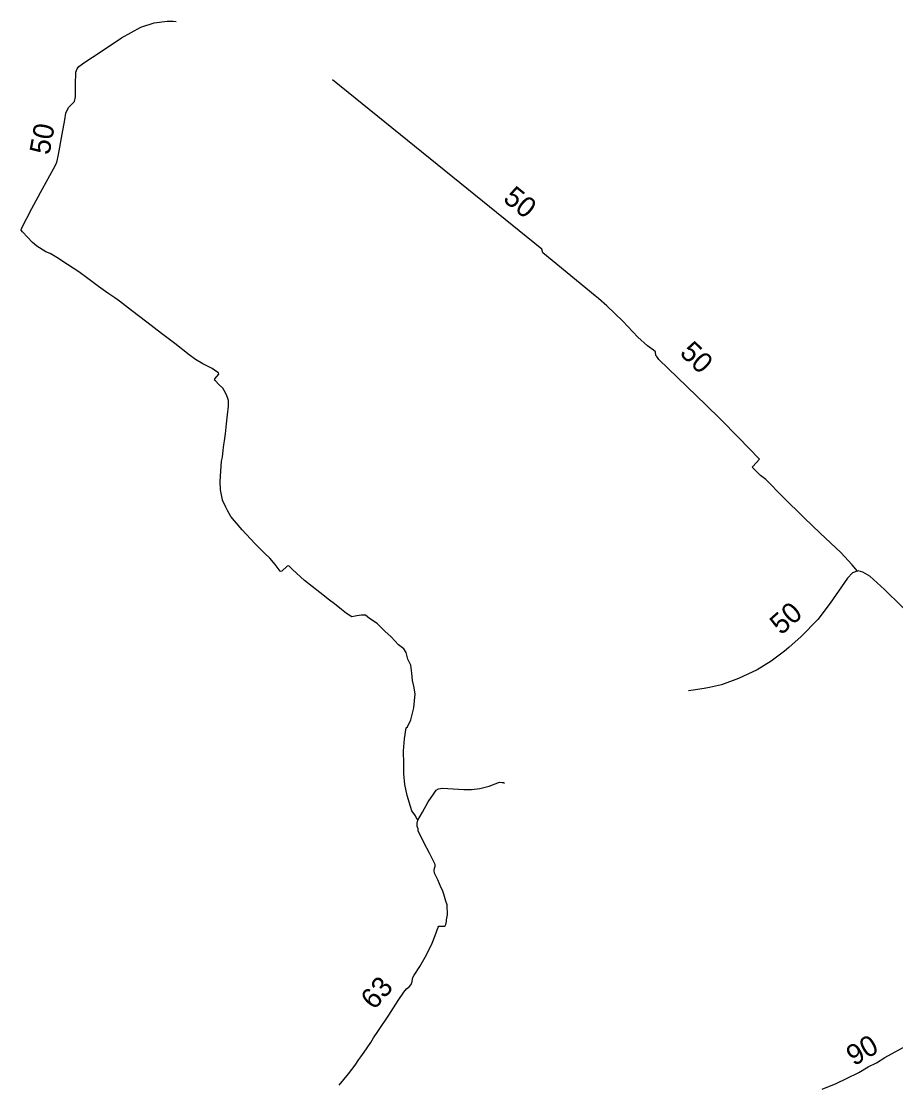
# Model space of a CAD drawing. Extents: x -444841 to -429545, y -1135312 to -1129851.
# Drawn here: x -442958 to -442616.2, y -1130962.1 to -1130546.7 of the extents above; entities that cross this region are included whole.
import ezdxf

# ---------------------------------------------------------------- set-up
doc = ezdxf.new("R2010")
doc.units = 0
for name, color, linetype in [('Vrstva 27', 7, 'Continuous'), ('Vrstva 30', 7, 'Continuous'), ('Vrstva 35', 7, 'Continuous'), ('Vrstva 38', 7, 'Continuous')]:
    doc.layers.add(name, color=color, linetype=linetype)

msp = doc.modelspace()

# ---------------------------------------------------------------- linework, layer by layer
at = {"layer": 'Vrstva 27'}
for points in [[(-442948.46, -1130636.83), (-442951.87, -1130634.68), (-442953.67, -1130633.16), (-442957.48, -1130629.04), (-442958.02, -1130628.37), (-442957.91, -1130627.65), (-442953.91, -1130619.91), (-442949.7, -1130612.21), (-442945.35, -1130604.37), (-442944.09, -1130601.96), (-442943.43, -1130598.8), (-442941.97, -1130590.85), (-442940.93, -1130585.18), (-442940.54, -1130582.6), (-442939.6, -1130580.36), (-442937.16, -1130578.11), (-442936.75, -1130576.27), (-442936.83, -1130571.51), (-442936.69, -1130566.66), (-442936.2, -1130565.3), (-442935.54, -1130564.39), (-442933.22, -1130562.69), (-442927.13, -1130558.77), (-442918.83, -1130553.17), (-442911.3, -1130548.95), (-442906.12, -1130547.37), (-442900.95, -1130546.69), (-442898.69, -1130546.72), (-442897.52, -1130546.8)], [(-442832.8, -1130776.69), (-442835.56, -1130774.5), (-442837.51, -1130772.98), (-442841.34, -1130769.98), (-442847.34, -1130765.3), (-442852.04, -1130761.08), (-442853.33, -1130759.71), (-442853.74, -1130759.58), (-442854.05, -1130759.7), (-442856.16, -1130761.61), (-442856.43, -1130761.77), (-442856.8, -1130761.66), (-442857.2, -1130761.13), (-442858.77, -1130759.04), (-442860.9, -1130756.63), (-442862.96, -1130754.69), (-442866.77, -1130750.91), (-442871.63, -1130745.45), (-442874.71, -1130741.99), (-442876.12, -1130740.32), (-442877.41, -1130738.02), (-442878.05, -1130736.62), (-442879.31, -1130733.89), (-442879.34, -1130733.82), (-442880.12, -1130729.93), (-442880.24, -1130726.64), (-442879.98, -1130722.59), (-442879.93, -1130720.68), (-442879.75, -1130718.71), (-442879.38, -1130717.07), (-442879.03, -1130714.37), (-442878.79, -1130712.29), (-442878.53, -1130710.66), (-442878.17, -1130707.99), (-442877.73, -1130704.1), (-442877.36, -1130700.56), (-442877.06, -1130697.13), (-442876.96, -1130694.99), (-442877.43, -1130693.8), (-442877.65, -1130693.09), (-442878.16, -1130691.99), (-442879.28, -1130690.17), (-442880.76, -1130688.64), (-442882.14, -1130687.3), (-442882.47, -1130686.97), (-442882.39, -1130686.52), (-442880.78, -1130684.71), (-442880.73, -1130684.65), (-442880.87, -1130684.18), (-442881.51, -1130683.78), (-442883.42, -1130682.5), (-442887.04, -1130680.61), (-442889.84, -1130678.89), (-442892.38, -1130677.09), (-442897.92, -1130672.65), (-442903.24, -1130668.76), (-442908.93, -1130664.36), (-442914.87, -1130659.82), (-442919.66, -1130656.15), (-442921.43, -1130654.84), (-442924.16, -1130653.04), (-442927.86, -1130650.36), (-442931.98, -1130647.32), (-442935.48, -1130644.67), (-442939.94, -1130641.73), (-442944.13, -1130639.08), (-442946.77, -1130637.43), (-442948.46, -1130636.83)], [(-442631.13, -1130761.67), (-442633.22, -1130759.18), (-442637.66, -1130754.31), (-442645.64, -1130746.8), (-442652, -1130740.82), (-442660.31, -1130732.56), (-442666.92, -1130725.88), (-442669.04, -1130724.31), (-442672.06, -1130721.31), (-442672.23, -1130721.05), (-442672.06, -1130720.75), (-442669.36, -1130717.93), (-442677.57, -1130709.44), (-442684.69, -1130702.29), (-442690.38, -1130696.7), (-442694.05, -1130693.1), (-442701.54, -1130685.97), (-442708.79, -1130678.92), (-442709.62, -1130677.75), (-442709.92, -1130677.36), (-442710.08, -1130675.98), (-442710.88, -1130675.26), (-442713.18, -1130673.54), (-442717, -1130670.16), (-442722.91, -1130663.98), (-442729.07, -1130658), (-442732.37, -1130655.02), (-442733.63, -1130654.08), (-442734.2, -1130653.65)], [(-442631.13, -1130761.67), (-442631.29, -1130761.72), (-442633.01, -1130762.3), (-442634.97, -1130764.35), (-442641.8, -1130774.19), (-442646.64, -1130780.62), (-442653.07, -1130787.17), (-442657.97, -1130791.51), (-442659.65, -1130793), (-442664.92, -1130796.9), (-442670.3, -1130800.21), (-442677.67, -1130803.68), (-442684.33, -1130806.12), (-442688.95, -1130807.11), (-442691.11, -1130807.51), (-442695.3, -1130808.24), (-442697.13, -1130808.46)], [(-442602.71, -1130779.69), (-442603.48, -1130779.37), (-442604.45, -1130779.32), (-442606.52, -1130781.39), (-442606.86, -1130781.47), (-442607.46, -1130781.28), (-442613.91, -1130775.41), (-442620.53, -1130768.88), (-442626.35, -1130763.61), (-442629.05, -1130762.08), (-442630.9, -1130761.59), (-442631.13, -1130761.67)], [(-442833.76, -1130962.64), (-442830.14, -1130958.16), (-442827.51, -1130954.79), (-442826, -1130952.6), (-442825.27, -1130951.56), (-442823.96, -1130949.76), (-442821.41, -1130945.88), (-442820.26, -1130944.13), (-442818.61, -1130941.62), (-442818.36, -1130941.23), (-442814.37, -1130935.29), (-442810.63, -1130929.55), (-442808.52, -1130926.29), (-442807.39, -1130925.01), (-442806.35, -1130924.23), (-442805.65, -1130923.28), (-442805.17, -1130922.08), (-442805.03, -1130921.18), (-442804.98, -1130920.58), (-442804.44, -1130919.67), (-442802.26, -1130916.22), (-442799.64, -1130911.63), (-442797.43, -1130907.11), (-442796.22, -1130904.05), (-442795.03, -1130900.85), (-442794.77, -1130900.47), (-442794.4, -1130900.43), (-442793.6, -1130900.42), (-442793.13, -1130900.43), (-442792.49, -1130900.44), (-442792.31, -1130900.36), (-442792.04, -1130899.8), (-442791.84, -1130898.69), (-442791.73, -1130897.99), (-442791.44, -1130896.02), (-442791.5, -1130892.12), (-442791.98, -1130890.66), (-442792.78, -1130887.95), (-442793.33, -1130886.43), (-442793.81, -1130885.44), (-442795.16, -1130882.39), (-442796.46, -1130879.79), (-442796.56, -1130878.68), (-442796.52, -1130877.84), (-442796.22, -1130877.14), (-442796.24, -1130876.36), (-442796.7, -1130875.34), (-442798.48, -1130871.95), (-442800.6, -1130867.78), (-442802.82, -1130863.18), (-442802.88, -1130862.46), (-442803.26, -1130861.45), (-442803.2, -1130860.18), (-442803.04, -1130858.98), (-442803.2, -1130858.69), (-442803.85, -1130857.32), (-442805.35, -1130855.35), (-442805.9, -1130853.69), (-442807.15, -1130849.37), (-442808.06, -1130845.03), (-442808.48, -1130840.85), (-442808.44, -1130837.12), (-442808.65, -1130831.96), (-442808.19, -1130827.16), (-442807.51, -1130822.86), (-442807.06, -1130822.47), (-442805.77, -1130819.78), (-442804.56, -1130815.08), (-442804.01, -1130809.6), (-442804.58, -1130806.68), (-442805.05, -1130804.47), (-442805.29, -1130801.49), (-442805.78, -1130798.43), (-442806.84, -1130796.11), (-442807.58, -1130793.48), (-442808.51, -1130792.09), (-442810.59, -1130790.46), (-442813.35, -1130787.28), (-442815.89, -1130785.07), (-442818.93, -1130782.19), (-442821.92, -1130780.16), (-442823.4, -1130778.91), (-442825, -1130778.91), (-442826.86, -1130779.16), (-442828.73, -1130779.47), (-442830.85, -1130778.23), (-442832.8, -1130776.69)], [(-442803.04, -1130858.98), (-442801.14, -1130855.89), (-442798.98, -1130851.88), (-442796.91, -1130848.81), (-442795.82, -1130847.35), (-442794.93, -1130846.77), (-442793.32, -1130846.5), (-442789.21, -1130846.72), (-442785.04, -1130847), (-442782.02, -1130847.09), (-442778.78, -1130846.68), (-442775.08, -1130845.69), (-442772.79, -1130844.82), (-442771.01, -1130844.17), (-442770.07, -1130844.26), (-442769.45, -1130844.32), (-442769.07, -1130844.5)], [(-442644.93, -1130964.24), (-442639.49, -1130962.01), (-442635.36, -1130959.97), (-442630.59, -1130957.63), (-442626.89, -1130955.51), (-442623.7, -1130953.84), (-442620.43, -1130951.84), (-442613.54, -1130948.05), (-442609.85, -1130946.56), (-442605.65, -1130944.6)]]:
    msp.add_lwpolyline(points, dxfattribs=at)
at = {"layer": 'Vrstva 35'}
msp.add_lwpolyline([(-442733.63, -1130654.08), (-442754.18, -1130637.18), (-442754.49, -1130635.74), (-442836.38, -1130569.65)], dxfattribs=at)

# ---------------------------------------------------------------- texts
at = {"layer": 'Vrstva 30'}
for s, rotation, p in [('50', 79.5937, (-442947.02, -1130599.19)), ('50', 315.8013, (-442700.97, -1130676.73)), ('50', 41.5318, (-442660.96, -1130786.91)), ('63', 48.8408, (-442820.02, -1130933.49)), ('90', 29.8115, (-442632.53, -1130955.3))]:
    msp.add_text(s, height=8, rotation=rotation, dxfattribs=at).set_placement(p)
at = {"layer": 'Vrstva 38'}
msp.add_text('50', height=8, rotation=321.0931, dxfattribs=at).set_placement((-442770.07, -1130616.74))

doc.saveas('drawing.dxf')
